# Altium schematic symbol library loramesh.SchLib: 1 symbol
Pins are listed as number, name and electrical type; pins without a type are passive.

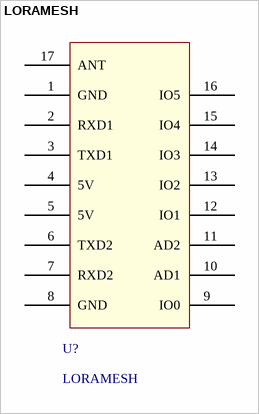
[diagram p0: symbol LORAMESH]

## LORAMESH
designator U?
Kit LoraMesh RADIOENGE
footprint LORAMESH (Kit LoraMesh)
pins: 1 GND, 2 RXD1, 3 TXD1, 4 5V, 5 5V, 6 TXD2, 7 RXD2, 8 GND, 9 IO0, 10 AD1, 11 AD2, 12 IO1, 13 IO2, 14 IO3, 15 IO4, 16 IO5, 17 ANT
